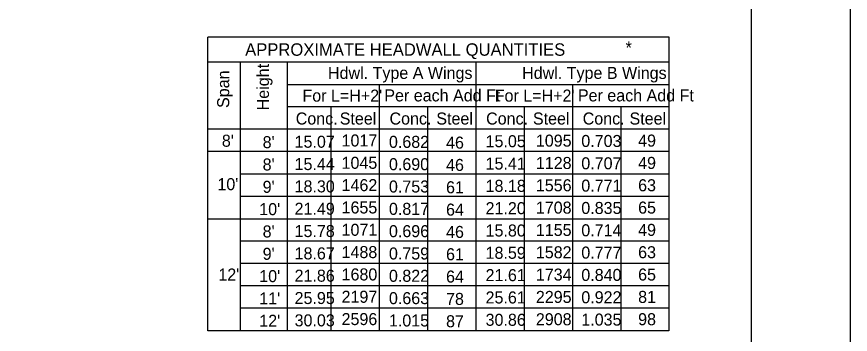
# Model space of a CAD drawing. Extents: x -0.08 to 2.83, y -0.03 to 1.92.
# Drawn here: x 1.959 to 2.833, y 0.859 to 1.192 of the extents above; entities that cross this region are included whole.
import ezdxf

# ---------------------------------------------------------------- set-up
doc = ezdxf.new("R2010")
doc.units = 0
for name, color, linetype in [('55', 7, 'Continuous'), ('57', 7, 'Continuous'), ('63', 7, 'Continuous')]:
    doc.layers.add(name, color=color, linetype=linetype)

msp = doc.modelspace()

# ---------------------------------------------------------------- linework, layer by layer
at = {"layer": '55'}
for p, q in [((2.15956, 0.86298), (2.15956, 1.17027)), ((2.64348, 1.17027), (2.15956, 1.17027)), ((2.64348, 0.86298), (2.64348, 1.17027)), ((2.64348, 1.14423), (2.15956, 1.14423)), ((2.19365, 0.86298), (2.19365, 1.14423)), ((2.24292, 0.86298), (2.24292, 1.14423)), ((2.44085, 0.86298), (2.44085, 1.14423)), ((2.64348, 1.1206), (2.24292, 1.1206)), ((2.33954, 0.86298), (2.33954, 1.1206)), ((2.54217, 0.86298), (2.54217, 1.1206)), ((2.64299, 1.09736), (2.24292, 1.09736)), ((2.28889, 0.86298), (2.28889, 1.09697)), ((2.3902, 0.86298), (2.3902, 1.09697)), ((2.49151, 0.86298), (2.49151, 1.09697)), ((2.59282, 0.86298), (2.59282, 1.09697)), ((2.64299, 1.07392), (2.15908, 1.07392)), ((2.64299, 1.05048), (2.15908, 1.05048)), ((2.64348, 1.02685), (2.19365, 1.02685)), ((2.64348, 1.00361), (2.19365, 1.00361)), ((2.15956, 0.97998), (2.64348, 0.97998)), ((2.64299, 0.95673), (2.19365, 0.95673)), ((2.64299, 0.93329), (2.19365, 0.93329)), ((2.64299, 0.90986), (2.19414, 0.90986)), ((2.64299, 0.88642), (2.19365, 0.88642)), ((2.64299, 0.86298), (2.15956, 0.86298))]:
    msp.add_line(p, q, dxfattribs=at)
at = {"layer": '63'}
msp.add_line((2.83333, 1.83333), (2.83333, 0), dxfattribs=at)
msp.add_lwpolyline([(0.16668, 0.06244), (0.16668, 1.77077), (2.72918, 1.77077), (2.72918, 0.10411), (2.56251, 0.10411), (2.56251, 0.14578), (2.07387, 0.14578), (2.07387, 0.06244)], close=True, dxfattribs=at)

# ---------------------------------------------------------------- texts
at = {"layer": '57'}
for s, height, p in [('APPROXIMATE HEADWALL QUANTITIES', 0.0130208, (2.19861, 1.1509)), ('*', 0.01302, (2.59754, 1.15285)), ('Hdwl. Type A Wings ', 0.0125875, (2.28549, 1.12666)), ('Hdwl. Type B Wings', 0.0125875, (2.48911, 1.12666)), ("For L=H+2'", 0.012588, (2.25869, 1.10288)), ('Per each Add Ft', 0.0125875, (2.34458, 1.1031)), ("For L=H+2'", 0.012588, (2.46037, 1.10288)), ('Per each Add Ft', 0.0125875, (2.54759, 1.1031)), ('Conc.', 0.012588, (2.25163, 1.07888)), ('Steel', 0.012588, (2.29779, 1.07888)), ('Conc.', 0.012588, (2.35001, 1.07888)), ('Conc.', 0.012588, (2.35001, 1.07888)), ('Steel', 0.012588, (2.39911, 1.07888)), ('Steel', 0.012588, (2.39911, 1.07888)), ('Conc.', 0.012588, (2.45132, 1.07888)), ('Conc.', 0.012588, (2.45132, 1.07888)), ('Steel', 0.012588, (2.50042, 1.07888)), ('Steel', 0.012588, (2.50042, 1.07888)), ('Conc.', 0.012588, (2.55263, 1.07888)), ('Conc.', 0.012588, (2.55263, 1.07888)), ('Steel', 0.012588, (2.60173, 1.07888)), ('Steel', 0.012588, (2.60173, 1.07888)), ("8'", 0.012588, (2.17417, 1.05561)), ("8'", 0.012588, (2.21695, 1.05412)), ('15.07', 0.012588, (2.25045, 1.05457)), ('1017', 0.012588, (2.29973, 1.05589)), ('0.682', 0.012588, (2.34942, 1.05444)), ('15.05', 0.012588, (2.45078, 1.05514)), ('1095', 0.012588, (2.50351, 1.05572)), ('0.703', 0.012588, (2.55118, 1.05536)), ('49', 0.012588, (2.61077, 1.05576)), ('46', 0.012588, (2.40931, 1.05364)), ("8'", 0.012588, (2.21695, 1.03074)), ('15.44', 0.012588, (2.25045, 1.03119)), ('1045', 0.012588, (2.29973, 1.03251)), ('0.690', 0.012588, (2.34942, 1.03106)), ('46', 0.012588, (2.40931, 1.03026)), ('15.41', 0.012588, (2.45078, 1.03176)), ('1128', 0.012588, (2.50351, 1.03234)), ('0.707', 0.012588, (2.55118, 1.03198)), ('49', 0.012588, (2.61077, 1.03238)), ("10'", 0.012588, (2.1695, 1.01013)), ("9'", 0.012588, (2.21695, 1.00736)), ('18.30', 0.012588, (2.25045, 1.00781)), ('1462', 0.012588, (2.29973, 1.00913)), ('0.753', 0.012588, (2.34942, 1.00768)), ('61', 0.012588, (2.40931, 1.00688)), ('18.18', 0.012588, (2.45078, 1.00838)), ('1556', 0.012588, (2.50351, 1.00896)), ('0.771', 0.012588, (2.55118, 1.0086)), ('63', 0.012588, (2.61077, 1.009)), ('21.49', 0.012588, (2.25045, 0.98443)), ('1655', 0.012588, (2.29973, 0.98575)), ('0.817', 0.012588, (2.34942, 0.9843)), ('21.20', 0.012588, (2.45078, 0.985)), ('1708', 0.012588, (2.50351, 0.98558)), ('0.835', 0.012588, (2.55118, 0.98522)), ('65', 0.012588, (2.61077, 0.98562)), ("10'", 0.012588, (2.21338, 0.98398)), ('64', 0.012588, (2.40931, 0.9835)), ("8'", 0.012588, (2.21695, 0.9606)), ('15.78', 0.012588, (2.25045, 0.96105)), ('1071', 0.012588, (2.29973, 0.96237)), ('0.696', 0.012588, (2.34942, 0.96092)), ('46', 0.012588, (2.40931, 0.96012)), ('15.80', 0.012588, (2.45078, 0.96162)), ('1155', 0.012588, (2.50351, 0.9622)), ('0.714', 0.012588, (2.55118, 0.96184)), ('49', 0.012588, (2.61077, 0.96224)), ("9'", 0.012588, (2.21695, 0.93722)), ('18.67', 0.012588, (2.25045, 0.93767)), ('1488', 0.012588, (2.29973, 0.93899)), ('0.759', 0.012588, (2.34942, 0.93754)), ('61', 0.012588, (2.40931, 0.93674)), ('18.59', 0.012588, (2.45078, 0.93824)), ('1582', 0.012588, (2.50351, 0.93882)), ('0.777', 0.012588, (2.55118, 0.93846)), ('63', 0.012588, (2.61077, 0.93886)), ("12'", 0.012588, (2.17049, 0.91553)), ('21.86', 0.012588, (2.25045, 0.91429)), ('1680', 0.012588, (2.29973, 0.91561)), ('0.822', 0.012588, (2.34942, 0.91416)), ('21.61', 0.012588, (2.45078, 0.91486)), ('1734', 0.012588, (2.50351, 0.91544)), ('0.840', 0.012588, (2.55118, 0.91508)), ('65', 0.012588, (2.61077, 0.91548)), ("10'", 0.012588, (2.21338, 0.91384)), ('64', 0.012588, (2.40931, 0.91336)), ("11'", 0.012588, (2.21338, 0.89046)), ('25.95', 0.012588, (2.25045, 0.89091)), ('2197', 0.012588, (2.29973, 0.89223)), ('0.663', 0.012588, (2.34942, 0.89078)), ('78', 0.012588, (2.40931, 0.88998)), ('25.61', 0.012588, (2.45078, 0.89148)), ('2295', 0.012588, (2.50351, 0.89206)), ('0.922', 0.012588, (2.55118, 0.8917)), ('81', 0.012588, (2.61077, 0.8921)), ("12'", 0.012588, (2.21338, 0.86708)), ('30.03', 0.012588, (2.25045, 0.86753)), ('2596', 0.012588, (2.29973, 0.86885)), ('1.015', 0.012588, (2.34942, 0.8674)), ('87', 0.012588, (2.40931, 0.8666)), ('30.86', 0.012588, (2.45078, 0.8681)), ('2908', 0.012588, (2.50351, 0.86868)), ('1.035', 0.012588, (2.55118, 0.86832)), ('98', 0.012588, (2.61077, 0.86872))]:
    msp.add_text(s, height=height, dxfattribs=at).set_placement(p)
for s, p in [('Height', (2.22356, 1.09371)), ('Span ', (2.18186, 1.09621))]:
    msp.add_text(s, height=0.012588, rotation=90, dxfattribs=at).set_placement(p)

doc.saveas('drawing.dxf')
